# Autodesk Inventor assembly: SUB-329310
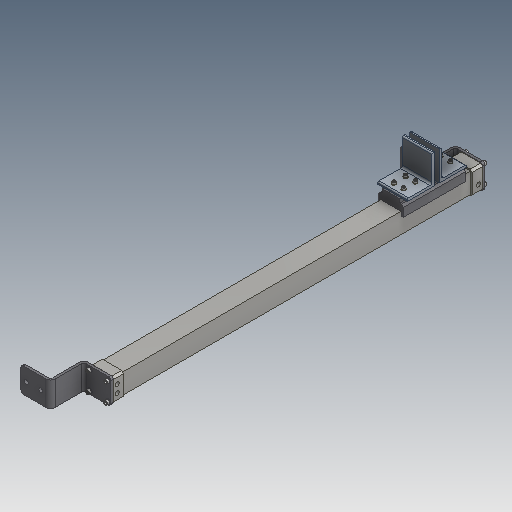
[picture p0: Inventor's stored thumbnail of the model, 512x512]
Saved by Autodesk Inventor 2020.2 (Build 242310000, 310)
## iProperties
Created: 2000-01
Part Number: SUB-329310
Document SubType Name: Assembly
Designer: cmcgourin
Mass: 9713.45 g
Surface Area: 3744.64 cm^2
Volume: 3169.94 cm^3
Density: 3.06424 g/cm^3
Control State: 0
Checked Out: False
Master: False
Shininess: 0.0
Length Units: 11272
Angle Units: 11279
Time Units: 11290
Mass Units: 11286
Length Display Precision: 3
Angle Display Precision: 2
Compacted: True
Dimensions: 6,3x41,6x6,1 in
Mass: 21,414 lb
DocNumber: SUB-329310.iam
Folder: 01 - Themengebiete\Simplification\01 - Packaging machine\
VDS_Category: 3D Komponenten
Density: 0.0
Volumn: 0.0
Area: 0.0
PropertySet Name: Model Information
Author: cmcgourin
Revision Number: -
Title: linear unit
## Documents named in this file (9)
- D:\07 - DEMODATEN\OTX 2019 - Dataset - UPDATE - Dez2019\Designs\07-Packing machine\SUB-329310.iam
- D:\07 - DEMODATEN\OTX 2019 - Dataset - UPDATE - Dez2019\Designs\07-Packing machine\A105211.iam
- D:\07 - DEMODATEN\OTX 2019 - Dataset - UPDATE - Dez2019\Designs\07-Packing machine\Parts\ADSK-011471.ipt
- D:\07 - DEMODATEN\OTX 2019 - Dataset - UPDATE - Dez2019\Designs\07-Packing machine\Parts\ADSK-011482.ipt
- D:\07 - DEMODATEN\OTX 2019 - Dataset - UPDATE - Dez2019\Designs\07-Packing machine\Parts\ADSK-011709.ipt
- D:\07 - DEMODATEN\OTX 2019 - Dataset - UPDATE - Dez2019\Content Center Files\de-DE\DIN 125-1  B\DIN 125-1 - B 5,3.ipt
- D:\07 - DEMODATEN\OTX 2019 - Dataset - UPDATE - Dez2019\Content Center Files\de-DE\ISO 4762(2)\ISO 4762 - M5 x 12ISO.ipt
- D:\07 - DEMODATEN\OTX 2019 - Dataset - UPDATE - Dez2019\Content Center Files\de-DE\DIN 125-1  B\DIN 125-1 - B 6,4.ipt
- D:\07 - DEMODATEN\OTX 2019 - Dataset - UPDATE - Dez2019\Content Center Files\de-DE\ISO 4762(2)\ISO 4762 - M6 x 20ISO.ipt
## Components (37 placed, 8 different names)
1. A105211 [sub-assembly] — Mate:1, Flush:1, Flush:2, Mate:2, Flush:3, Flush:4, Mate:7, Mate:9, Passend:10, Passend:11, Passend:12, Passend:13
2. ADSK-011471:1 — Mate:1, Flush:1, Flush:2, Passend:31, Passend:33, Passend:35, Passend:37
3. 500532Ript:1 — Mate:2, Flush:3, Flush:4
4. ADSK-011709:1 — Mate:7, Passend:12, Passend:13
5. ADSK-011709:2 — Mate:9, Passend:10, Passend:11
6. DIN 125-1 B B 5,3:1
7. DIN 125-1 B B 5,3:2
8. DIN 125-1 B B 5,3:3 — Passend:23, Passend:25, Passend:27, Passend:29
9. DIN 125-1 B B 5,3:4
10. DIN 125-1 B B 5,3:5
11. DIN 125-1 B B 5,3:6 — Passend:15, Passend:17, Passend:19, Passend:21
12. DIN 125-1 B B 5,3:7
13. DIN 125-1 B B 5,3:8
14. ISO 4762 M5 x 12:1 — Passend:15
15. ISO 4762 M5 x 12:2 — Passend:17
16. ISO 4762 M5 x 12:3 — Passend:19
17. ISO 4762 M5 x 12:4 — Passend:21
18. ISO 4762 M5 x 12:5 — Passend:23
19. ISO 4762 M5 x 12:6 — Passend:25
20. ISO 4762 M5 x 12:7 — Passend:27
21. ISO 4762 M5 x 12:8 — Passend:29
22. DIN 125-1 B B 6,4:1 — Passend:47, Passend:49, Passend:51, Passend:53
23. DIN 125-1 B B 6,4:2
24. DIN 125-1 B B 6,4:3
25. DIN 125-1 B B 6,4:4
26. DIN 125-1 B B 6,4:5 — Passend:31, Passend:39, Passend:41, Passend:43, Passend:45
27. DIN 125-1 B B 6,4:6 — Passend:33
28. DIN 125-1 B B 6,4:7 — Passend:35
29. DIN 125-1 B B 6,4:8 — Passend:37
30. ISO 4762 M6 x 20:1 — Passend:39
31. ISO 4762 M6 x 20:2 — Passend:41
32. ISO 4762 M6 x 20:3 — Passend:43
33. ISO 4762 M6 x 20:4 — Passend:45
34. ISO 4762 M6 x 20:5 — Passend:47
35. ISO 4762 M6 x 20:6 — Passend:49
36. ISO 4762 M6 x 20:7 — Passend:51
37. ISO 4762 M6 x 20:8 — Passend:53
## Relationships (32: Mate 28, Flush 4)
- Mate:1: A105211 ↔ ADSK-011471:1
- Flush:1: A105211 ↔ ADSK-011471:1
- Flush:2: A105211 ↔ ADSK-011471:1
- Mate:2: A105211 ↔ 500532Ript:1
- Flush:3: A105211 ↔ 500532Ript:1
- Flush:4: A105211 ↔ 500532Ript:1
- Mate:7: A105211 ↔ ADSK-011709:1
- Mate:9: A105211 ↔ ADSK-011709:2
- Passend:10 [Mate]: A105211 ↔ ADSK-011709:2
- Passend:11 [Mate]: A105211 ↔ ADSK-011709:2
- Passend:12 [Mate]: A105211 ↔ ADSK-011709:1
- Passend:13 [Mate]: A105211 ↔ ADSK-011709:1
- Passend:15 [Mate]: DIN 125-1 B B 5,3:6 ↔ ISO 4762 M5 x 12:1
- Passend:17 [Mate]: DIN 125-1 B B 5,3:6 ↔ ISO 4762 M5 x 12:2
- Passend:19 [Mate]: DIN 125-1 B B 5,3:6 ↔ ISO 4762 M5 x 12:3
- Passend:21 [Mate]: DIN 125-1 B B 5,3:6 ↔ ISO 4762 M5 x 12:4
- Passend:23 [Mate]: DIN 125-1 B B 5,3:3 ↔ ISO 4762 M5 x 12:5
- Passend:25 [Mate]: DIN 125-1 B B 5,3:3 ↔ ISO 4762 M5 x 12:6
- Passend:27 [Mate]: DIN 125-1 B B 5,3:3 ↔ ISO 4762 M5 x 12:7
- Passend:29 [Mate]: DIN 125-1 B B 5,3:3 ↔ ISO 4762 M5 x 12:8
- Passend:31 [Mate]: ADSK-011471:1 ↔ DIN 125-1 B B 6,4:5
- Passend:33 [Mate]: ADSK-011471:1 ↔ DIN 125-1 B B 6,4:6
- Passend:35 [Mate]: ADSK-011471:1 ↔ DIN 125-1 B B 6,4:7
- Passend:37 [Mate]: ADSK-011471:1 ↔ DIN 125-1 B B 6,4:8
- Passend:39 [Mate]: DIN 125-1 B B 6,4:5 ↔ ISO 4762 M6 x 20:1
- Passend:41 [Mate]: DIN 125-1 B B 6,4:5 ↔ ISO 4762 M6 x 20:2
- Passend:43 [Mate]: DIN 125-1 B B 6,4:5 ↔ ISO 4762 M6 x 20:3
- Passend:45 [Mate]: DIN 125-1 B B 6,4:5 ↔ ISO 4762 M6 x 20:4
- Passend:47 [Mate]: DIN 125-1 B B 6,4:1 ↔ ISO 4762 M6 x 20:5
- Passend:49 [Mate]: DIN 125-1 B B 6,4:1 ↔ ISO 4762 M6 x 20:6
- Passend:51 [Mate]: DIN 125-1 B B 6,4:1 ↔ ISO 4762 M6 x 20:7
- Passend:53 [Mate]: DIN 125-1 B B 6,4:1 ↔ ISO 4762 M6 x 20:8
